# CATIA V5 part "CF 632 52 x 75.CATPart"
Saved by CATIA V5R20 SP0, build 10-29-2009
Part number: CF 632 52 x 75
Definition: NONE
Nomenclature: CF 632 52 x 75
Source: Unknown
Description: CF 632 52 x 75
Bounding box of the stored display mesh (mm): x -13 to 62, y -39.5 to 39.5, z -39.5 to 39.5
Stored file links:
  C:\Users\Utente\Desktop\IO LAVORO\3D X SITO CF\X SITO\CF 632\CF 632 52 x 75.CATPart
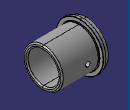
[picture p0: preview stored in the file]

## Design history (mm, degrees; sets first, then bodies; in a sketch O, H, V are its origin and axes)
Body1 "CF 632 52 x 75" (main body)
  Solid1: solid without history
